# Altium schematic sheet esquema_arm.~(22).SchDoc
size A4
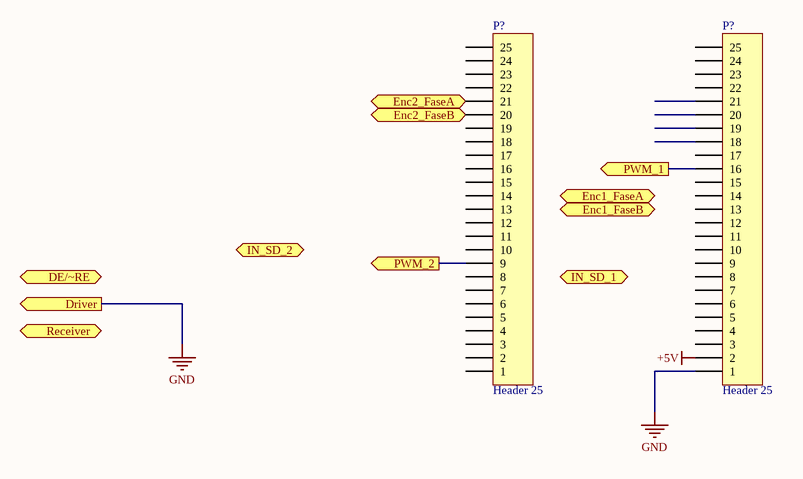
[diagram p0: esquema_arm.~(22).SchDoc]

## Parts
(Parts that share a designator on the sheet are numbered #1, #2 ... from top to bottom, then left to right.)
P?#1  Header 25  [HDR1X25]
P?#2  Header 25  [HDR1X25]

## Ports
DE/~RE (out), Driver (out), Enc1_FaseA (in), Enc1_FaseB (in), Enc2_FaseA (in), Enc2_FaseB (in), IN_SD_1 (out), IN_SD_2 (out), PWM_1 (out), PWM_2 (out), Receiver (in)

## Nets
+5V: P?#2.2
GND: P?#2.1 ; port Driver
Enc2_FaseA: P?#1.21 ; port Enc2_FaseA
Enc2_FaseB: P?#1.20 ; port Enc2_FaseB
PWM_1: P?#2.16 ; port PWM_1
PWM_2: P?#1.9 ; port PWM_2

Not connected (* = marked no-connect by the designer): P?#1 1 2 3 4 5 6 7 8 10 11 12 13 14 15 16 17 18 19 22 23 24 25; P?#2 3 4 5 6 7 8 9 10 11 12 13 14 15 17 18 19 20 21 22 23 24 25

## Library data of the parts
P?#1 P?#2 = Header 25: Header, 25-Pin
